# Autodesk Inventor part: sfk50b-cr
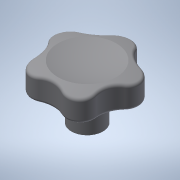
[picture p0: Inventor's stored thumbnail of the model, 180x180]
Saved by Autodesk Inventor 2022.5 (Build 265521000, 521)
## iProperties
Created: 2016-12
Part Number: sfk50b-cr
Material: 一般
Document SubType Name: Modeling
Designer: imaocorp
Density: 1 g/cm^3
Appearance: 既定
Author: imaocorp
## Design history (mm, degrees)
node "sfk50b-cr.x_t1"
node "sfk50b-cr"
node "Base1"
